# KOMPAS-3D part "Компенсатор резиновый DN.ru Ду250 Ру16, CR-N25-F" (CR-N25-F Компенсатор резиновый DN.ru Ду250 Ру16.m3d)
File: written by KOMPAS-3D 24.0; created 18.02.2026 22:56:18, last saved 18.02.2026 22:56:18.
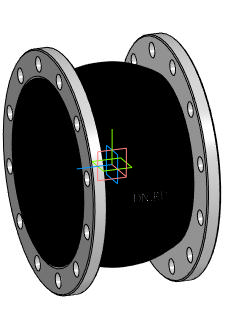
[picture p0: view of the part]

Document properties: Автор: DN.RU; Полное имя файла: D:\PROJECT CAD\DN.RU\...178(1)(ACTUALE). CR-N25-F Компенсатор резиновый DN.ru Ру10-16\DN250_PN16\CR-N25-F Компенсатор резиновый DN.ru Ду250 Ру16.m3d

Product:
- Body: Твердое тело2  | qty 1
    Масса: 71.141217
- Part/product: Компенсатор резиновый DN.ru Ду250 Ру16  | designation CR-N25-F
    Масса: 25
    Раздел спецификации: Прочие изделия
    Комментарий: D140-02401
    Примечание: D140-02401
    additional columns: Типовые

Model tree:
1. Твердое тело2  (labels: Твердое тело2)

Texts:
  CR-N25-F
